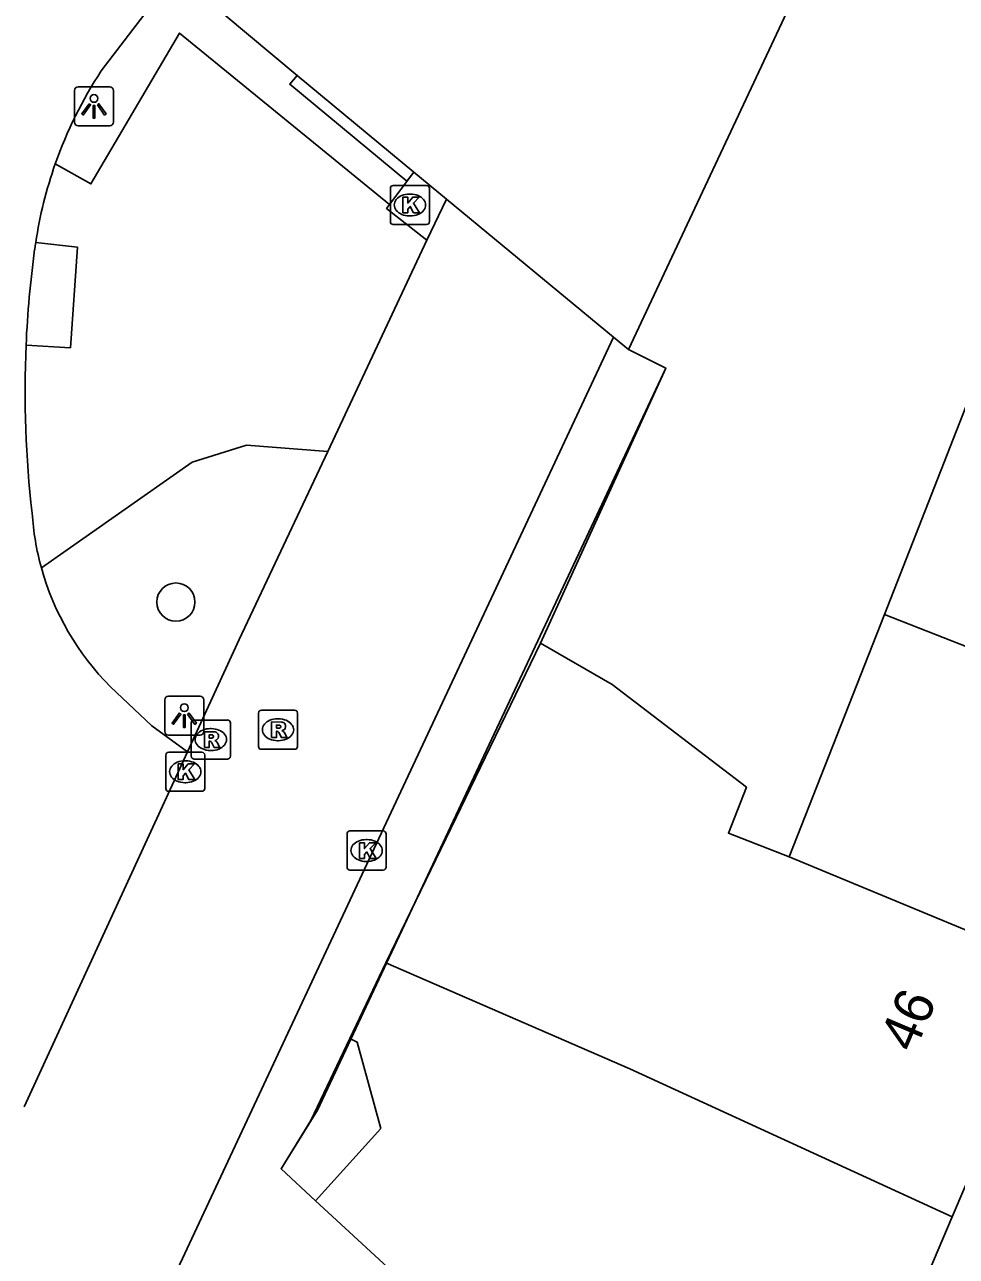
# Model space of a CAD drawing. Extents: x 160107 to 160928, y 382056 to 382918.
# Drawn here: x 160855.17 to 160879.01, y 382763.43 to 382794.93 of the extents above; entities that cross this region are included whole.
import ezdxf

# ---------------------------------------------------------------- set-up
doc = ezdxf.new("R2010")
doc.units = 0
for name, color, linetype in [('IMGEO_Boom', 7, 'Continuous'), ('IMGEO_Groenvoorziening', 7, 'Continuous'), ('IMGEO_Haag', 7, 'Continuous'), ('IMGEO_Kolk', 7, 'Continuous'), ('IMGEO_Lichtpunt', 7, 'Continuous'), ('IMGEO_Muur', 7, 'Continuous'), ('IMGEO_Pand', 7, 'Continuous'), ('IMGEO_Pand_nummerreeks', 7, 'Continuous'), ('IMGEO_Rijbaan_lokaal_open', 7, 'Continuous'), ('IMGEO_Rioolput', 7, 'Continuous'), ('IMGEO_Voetpad_open', 7, 'Continuous')]:
    doc.layers.add(name, color=color, linetype=linetype)

msp = doc.modelspace()

# ---------------------------------------------------------------- linework, layer by layer
at = {"layer": 'IMGEO_Boom'}
msp.add_circle((160859.037, 382780.163), 0.489, dxfattribs=at)
at = {"layer": 'IMGEO_Groenvoorziening'}
for points in [[(160865.463, 382789.419), (160864.429, 382790.234), (160864.504, 382790.333)], [(160855.596, 382781.037), (160859.451, 382783.744), (160860.847, 382784.179), (160862.922, 382784.019)]]:
    msp.add_lwpolyline(points, dxfattribs=at)
at = {"layer": 'IMGEO_Haag'}
for points in [[(160864.504, 382790.333), (160859.133, 382794.716), (160856.862, 382790.857), (160855.952, 382791.372)], [(160865.13, 382791.163), (160864.948, 382790.93), (160861.953, 382793.407), (160862.138, 382793.636)], [(160864.504, 382790.333), (160865.13, 382791.163)], [(160855.204, 382786.738), (160856.339, 382786.668), (160856.518, 382789.241), (160855.451, 382789.363)]]:
    msp.add_lwpolyline(points, dxfattribs=at)
at = {"layer": 'IMGEO_Kolk'}
for p, q in [((160864.526, 382789.894), (160864.526, 382790.746)), ((160864.601, 382790.82), (160865.453, 382790.82)), ((160865.527, 382790.746), (160865.527, 382789.894)), ((160865.014, 382790.6), (160865.039, 382790.6)), ((160865.453, 382789.82), (160864.601, 382789.82)), ((160865.037, 382790.04), (160865.012, 382790.04)), ((160858.778, 382775.398), (160858.778, 382776.25)), ((160858.853, 382776.324), (160859.705, 382776.324)), ((160859.779, 382776.25), (160859.779, 382775.398)), ((160859.266, 382776.104), (160859.291, 382776.104)), ((160859.705, 382775.324), (160858.853, 382775.324)), ((160859.289, 382775.544), (160859.264, 382775.544)), ((160863.417, 382773.383), (160863.417, 382774.235)), ((160863.492, 382774.309), (160864.344, 382774.309)), ((160863.905, 382774.089), (160863.93, 382774.089)), ((160864.418, 382774.235), (160864.418, 382773.383)), ((160863.928, 382773.529), (160863.903, 382773.529)), ((160864.344, 382773.309), (160863.492, 382773.309))]:
    msp.add_line(p, q, dxfattribs=at)
for points in [[(160864.526, 382789.894), (160864.526, 382790.746)], [(160864.601, 382790.82), (160865.453, 382790.82)], [(160865.527, 382790.746), (160865.527, 382789.894)], [(160864.847, 382790.52), (160864.97, 382790.52), (160864.97, 382790.369), (160865.1, 382790.52), (160865.264, 382790.52), (160865.118, 382790.369), (160865.271, 382790.12), (160865.119, 382790.12), (160865.034, 382790.284), (160864.97, 382790.217), (160864.97, 382790.12), (160864.847, 382790.12), (160864.847, 382790.52)], [(160865.453, 382789.82), (160864.601, 382789.82)], [(160858.778, 382775.398), (160858.778, 382776.25)], [(160858.853, 382776.324), (160859.705, 382776.324)], [(160859.779, 382776.25), (160859.779, 382775.398)], [(160859.099, 382776.024), (160859.222, 382776.024), (160859.222, 382775.873), (160859.352, 382776.024), (160859.516, 382776.024), (160859.37, 382775.873), (160859.523, 382775.624), (160859.371, 382775.624), (160859.286, 382775.788), (160859.222, 382775.721), (160859.222, 382775.624), (160859.099, 382775.624), (160859.099, 382776.024)], [(160859.705, 382775.324), (160858.853, 382775.324)], [(160863.417, 382773.383), (160863.417, 382774.235)], [(160863.492, 382774.309), (160864.344, 382774.309)], [(160863.738, 382774.009), (160863.861, 382774.009), (160863.861, 382773.858), (160863.991, 382774.009), (160864.155, 382774.009), (160864.009, 382773.858), (160864.162, 382773.609), (160864.01, 382773.609), (160863.925, 382773.773), (160863.861, 382773.706), (160863.861, 382773.609), (160863.738, 382773.609), (160863.738, 382774.009)], [(160864.418, 382774.235), (160864.418, 382773.383)], [(160864.344, 382773.309), (160863.492, 382773.309)]]:
    msp.add_lwpolyline(points, dxfattribs=at)
for centre, start, end in [((160864.603, 382790.744), 91.552, 178.448), ((160864.603, 382790.744), 91.552, 178.448), ((160865.451, 382790.744), 1.552, 88.448), ((160865.451, 382790.744), 1.552, 88.448), ((160864.603, 382789.896), 181.552, 268.448), ((160864.603, 382789.896), 181.552, 268.448), ((160865.451, 382789.896), 271.552, 358.448), ((160865.451, 382789.896), 271.552, 358.448), ((160858.855, 382776.248), 91.552, 178.448), ((160858.855, 382776.248), 91.552, 178.448), ((160859.703, 382776.248), 1.552, 88.448), ((160859.703, 382776.248), 1.552, 88.448), ((160858.855, 382775.4), 181.552, 268.448), ((160858.855, 382775.4), 181.552, 268.448), ((160859.703, 382775.4), 271.552, 358.448), ((160859.703, 382775.4), 271.552, 358.448), ((160863.494, 382774.233), 91.552, 178.448), ((160863.494, 382774.233), 91.552, 178.448), ((160864.342, 382774.233), 1.552, 88.448), ((160864.342, 382774.233), 1.552, 88.448), ((160863.494, 382773.385), 181.552, 268.448), ((160863.494, 382773.385), 181.552, 268.448), ((160864.342, 382773.385), 271.552, 358.448), ((160864.342, 382773.385), 271.552, 358.448)]:
    msp.add_arc(centre, 0.0765, start, end, dxfattribs=at)
for centre, major_axis, ratio, start_param, end_param in [((160865.013, 382790.32), (-0.387, 0.002), 0.722429, 4.712389, 7.853982), ((160865.038, 382790.32), (-0.39, 0.002), 0.717154, 1.570796, 4.712389), ((160859.265, 382775.824), (-0.387, 0.002), 0.722429, 4.712389, 7.853982), ((160859.29, 382775.824), (-0.39, 0.002), 0.717154, 1.570796, 4.712389), ((160863.904, 382773.809), (-0.387, 0.002), 0.722429, 4.712389, 7.853982), ((160863.929, 382773.809), (-0.39, 0.002), 0.717154, 1.570796, 4.712389)]:
    msp.add_ellipse(centre, major_axis=major_axis, ratio=ratio, start_param=start_param, end_param=end_param, dxfattribs=at)
at = {"layer": 'IMGEO_Lichtpunt'}
for p, q in [((160856.442, 382793.247), (160856.442, 382792.44)), ((160856.442, 382793.247), (160856.442, 382792.44)), ((160857.344, 382793.342), (160856.536, 382793.342)), ((160857.344, 382793.342), (160856.536, 382793.342)), ((160857.438, 382792.44), (160857.438, 382793.247)), ((160857.438, 382792.44), (160857.438, 382793.247)), ((160856.536, 382792.346), (160857.344, 382792.346)), ((160856.536, 382792.346), (160857.344, 382792.346)), ((160858.753, 382777.663), (160858.753, 382776.856)), ((160858.753, 382777.663), (160858.753, 382776.856)), ((160859.655, 382777.758), (160858.847, 382777.758)), ((160859.655, 382777.758), (160858.847, 382777.758)), ((160859.749, 382776.856), (160859.749, 382777.663)), ((160859.749, 382776.856), (160859.749, 382777.663)), ((160858.847, 382776.762), (160859.655, 382776.762)), ((160858.847, 382776.762), (160859.655, 382776.762))]:
    msp.add_line(p, q, dxfattribs=at)
for points in [[(160856.816, 382792.911), (160856.855, 382792.883), (160856.667, 382792.621), (160856.629, 382792.648), (160856.816, 382792.911)], [(160857.028, 382792.883), (160857.066, 382792.91), (160857.253, 382792.648), (160857.214, 382792.62), (160857.028, 382792.883)], [(160856.918, 382792.863), (160856.965, 382792.863), (160856.965, 382792.541), (160856.918, 382792.541), (160856.918, 382792.863)], [(160859.127, 382777.327), (160859.166, 382777.299), (160858.978, 382777.037), (160858.94, 382777.064), (160859.127, 382777.327)], [(160859.229, 382777.279), (160859.276, 382777.279), (160859.276, 382776.957), (160859.229, 382776.957), (160859.229, 382777.279)], [(160859.339, 382777.299), (160859.377, 382777.326), (160859.564, 382777.064), (160859.525, 382777.036), (160859.339, 382777.299)]]:
    msp.add_lwpolyline(points, dxfattribs=at)
for centre in [(160856.941, 382793.045), (160859.252, 382777.461)]:
    msp.add_circle(centre, 0.0994, dxfattribs=at)
for centre, start, end in [((160856.536, 382793.247), 90, 180), ((160856.536, 382793.247), 90, 180), ((160857.344, 382793.247), 0, 90), ((160857.344, 382793.247), 0, 90), ((160856.536, 382792.44), 180, 270), ((160856.536, 382792.44), 180, 270), ((160857.344, 382792.44), 270, 0), ((160857.344, 382792.44), 270, 360), ((160858.847, 382777.663), 90, 180), ((160858.847, 382777.663), 90, 180), ((160859.655, 382777.663), 0, 90), ((160859.655, 382777.663), 0, 90), ((160858.847, 382776.856), 180, 270), ((160858.847, 382776.856), 180, 270), ((160859.655, 382776.856), 270, 0), ((160859.655, 382776.856), 270, 360)]:
    msp.add_arc(centre, 0.0946, start, end, dxfattribs=at)
at = {"layer": 'IMGEO_Muur'}
for points in [[(160865.463, 382789.419), (160865.965, 382790.473)], [(160862.922, 382784.019), (160865.463, 382789.419)], [(160870.234, 382786.936), (160864.175, 382773.992)], [(160870.621, 382786.622), (160871.573, 382786.148), (160862.66, 382767.165), (160861.728, 382765.67), (160862.611, 382764.85)], [(160860.656, 382779.204), (160862.922, 382784.019)]]:
    msp.add_lwpolyline(points, dxfattribs=at)
at = {"layer": 'IMGEO_Pand'}
for points in [[(160878.006, 382802.366), (160870.621, 382786.622)], [(160859.026, 382796.237), (160862.138, 382793.636)], [(160862.138, 382793.636), (160865.13, 382791.163)], [(160865.13, 382791.163), (160865.965, 382790.473)], [(160870.234, 382786.936), (160865.965, 382790.473)], [(160870.621, 382786.622), (160870.234, 382786.936)], [(160877.168, 382779.848), (160879.654, 382786.178)], [(160874.732, 382773.645), (160877.168, 382779.848)], [(160877.168, 382779.848), (160886.026, 382776.373)], [(160864.409, 382770.935), (160868.368, 382779.113)], [(160868.368, 382779.113), (160870.2, 382778.054), (160873.638, 382775.428), (160873.177, 382774.255), (160874.732, 382773.645)], [(160874.732, 382773.645), (160881.607, 382770.804)], [(160863.489, 382768.997), (160864.409, 382770.935)], [(160878.904, 382764.441), (160870.655, 382768.224), (160864.409, 382770.935)], [(160881.607, 382770.804), (160879.55, 382765.961), (160878.904, 382764.441)], [(160862.611, 382764.85), (160864.28, 382766.698), (160863.68, 382768.906), (160863.489, 382768.997)], [(160875.47, 382756.281), (160868.142, 382759.756), (160862.611, 382764.85)], [(160878.904, 382764.441), (160877.92, 382762.125), (160875.47, 382756.281)]]:
    msp.add_lwpolyline(points, dxfattribs=at)
at = {"layer": 'IMGEO_Rijbaan_lokaal_open'}
for points in [[(160865.965, 382790.473), (160865.463, 382789.419)], [(160865.463, 382789.419), (160862.922, 382784.019)], [(160858.349, 382761.529), (160864.175, 382773.992), (160870.234, 382786.936)], [(160862.922, 382784.019), (160860.656, 382779.204), (160859.334, 382776.335)], [(160859.334, 382776.335), (160855.156, 382767.252)]]:
    msp.add_lwpolyline(points, dxfattribs=at)
at = {"layer": 'IMGEO_Rioolput'}
for p, q in [((160861.15, 382776.472), (160861.15, 382777.324)), ((160861.225, 382777.398), (160862.077, 382777.398)), ((160861.638, 382777.178), (160861.663, 382777.178)), ((160862.151, 382777.324), (160862.151, 382776.472)), ((160859.431, 382776.221), (160859.431, 382777.073)), ((160859.506, 382777.147), (160860.358, 382777.147)), ((160859.919, 382776.927), (160859.944, 382776.927)), ((160860.432, 382777.073), (160860.432, 382776.221)), ((160861.661, 382776.618), (160861.636, 382776.618)), ((160859.942, 382776.367), (160859.917, 382776.367)), ((160862.077, 382776.398), (160861.225, 382776.398)), ((160860.358, 382776.147), (160859.506, 382776.147))]:
    msp.add_line(p, q, dxfattribs=at)
for points in [[(160861.15, 382776.472), (160861.15, 382777.324)], [(160861.225, 382777.398), (160862.077, 382777.398)], [(160862.151, 382777.324), (160862.151, 382776.472)], [(160859.431, 382776.221), (160859.431, 382777.073)], [(160859.506, 382777.147), (160860.358, 382777.147)], [(160860.02, 382776.845), (160859.768, 382776.847), (160859.768, 382776.447)], [(160860.432, 382777.073), (160860.432, 382776.221)], [(160861.739, 382777.096), (160861.487, 382777.098), (160861.487, 382776.698)], [(160861.487, 382776.698), (160861.611, 382776.698), (160861.611, 382776.86), (160861.622, 382776.86)], [(160861.665, 382777.017), (160861.611, 382777.017), (160861.611, 382776.936)], [(160861.611, 382776.936), (160861.663, 382776.936)], [(160859.768, 382776.447), (160859.892, 382776.447), (160859.892, 382776.609), (160859.903, 382776.609)], [(160859.946, 382776.766), (160859.892, 382776.766), (160859.892, 382776.685)], [(160859.892, 382776.685), (160859.944, 382776.685)], [(160859.95, 382776.58), (160860.021, 382776.447), (160860.161, 382776.447), (160860.096, 382776.573)], [(160861.669, 382776.831), (160861.74, 382776.698), (160861.88, 382776.698), (160861.815, 382776.824)], [(160862.077, 382776.398), (160861.225, 382776.398)], [(160860.358, 382776.147), (160859.506, 382776.147)]]:
    msp.add_lwpolyline(points, dxfattribs=at)
for centre, radius, start, end in [((160861.227, 382777.322), 0.0765, 91.552, 178.448), ((160861.227, 382777.322), 0.0765, 91.552, 178.448), ((160862.075, 382777.322), 0.0765, 1.552, 88.448), ((160862.075, 382777.322), 0.0765, 1.552, 88.448), ((160859.508, 382777.071), 0.0765, 91.552, 178.448), ((160859.508, 382777.071), 0.0765, 91.552, 178.448), ((160860.019, 382776.735), 0.109, 350.3612, 89.416), ((160860.356, 382777.071), 0.0765, 1.552, 88.448), ((160860.356, 382777.071), 0.0765, 1.552, 88.448), ((160861.621, 382776.807), 0.0533, 26.0293, 88.6989), ((160861.647, 382777.125), 0.19, 274.7715, 282.9687), ((160861.671, 382776.921), 0.0964, 77.0061, 93.1865), ((160861.685, 382776.978), 0.0378, 276.6634, 79.6772), ((160861.738, 382776.986), 0.109, 350.3612, 89.416), ((160861.736, 382776.986), 0.112, 277.5842, 350.9817), ((160861.72, 382776.771), 0.108, 29.5134, 73.7905), ((160859.902, 382776.556), 0.0533, 26.0293, 88.6989), ((160859.928, 382776.874), 0.19, 274.7715, 282.9687), ((160859.952, 382776.67), 0.0964, 77.0061, 93.1865), ((160859.966, 382776.727), 0.0378, 276.6634, 79.6772), ((160860.017, 382776.735), 0.112, 277.5842, 350.9817), ((160860.001, 382776.52), 0.108, 29.5134, 73.7905), ((160859.508, 382776.223), 0.0765, 181.552, 268.448), ((160859.508, 382776.223), 0.0765, 181.552, 268.448), ((160860.356, 382776.223), 0.0765, 271.552, 358.448), ((160860.356, 382776.223), 0.0765, 271.552, 358.448), ((160861.227, 382776.474), 0.0765, 181.552, 268.448), ((160861.227, 382776.474), 0.0765, 181.552, 268.448), ((160862.075, 382776.474), 0.0765, 271.552, 358.448), ((160862.075, 382776.474), 0.0765, 271.552, 358.448)]:
    msp.add_arc(centre, radius, start, end, dxfattribs=at)
for centre, major_axis, ratio, start_param, end_param in [((160861.637, 382776.898), (-0.387, 0.002), 0.722429, 4.712389, 7.853982), ((160861.662, 382776.898), (-0.39, 0.002), 0.717154, 1.570796, 4.712389), ((160859.918, 382776.647), (-0.387, 0.002), 0.722429, 4.712389, 7.853982), ((160859.943, 382776.647), (-0.39, 0.002), 0.717154, 1.570796, 4.712389)]:
    msp.add_ellipse(centre, major_axis=major_axis, ratio=ratio, start_param=start_param, end_param=end_param, dxfattribs=at)
at = {"layer": 'IMGEO_Voetpad_open'}
for points in [[(160859.026, 382796.237), (160857.127, 382793.749)], [(160855.451, 382789.363), (160855.437, 382789.271), (160855.424, 382789.179)], [(160870.621, 382786.622), (160871.573, 382786.148), (160868.368, 382779.113)], [(160857.366, 382777.995), (160858.418, 382776.997), (160859.334, 382776.335)], [(160862.611, 382764.85), (160861.728, 382765.67), (160862.495, 382766.9), (160863.489, 382768.997)]]:
    msp.add_lwpolyline(points, dxfattribs=at)
for centre, radius, start, end in [((160878.164, 382788.105), 25.296, 153.9548, 168.4544), ((160866.373, 382787.7), 11.049, 146.8044, 160.5873), ((160866.317, 382787.72), 10.99, 160.5919, 171.4028), ((160881.902, 382785.562), 26.724, 172.2218, 177.4783), ((160882.096, 382785.549), 26.918, 177.4685, 186.6347), ((160862.288, 382782.894), 6.944, 183.7578, 195.5113), ((160862.285, 382782.893), 6.942, 195.5089, 224.8774)]:
    msp.add_arc(centre, radius, start, end, dxfattribs=at)

# ---------------------------------------------------------------- texts
at = {"layer": 'IMGEO_Pand_nummerreeks'}
msp.add_text('46', height=1, rotation=66.9845, dxfattribs=at).set_placement((160877.936, 382768.607))

doc.saveas('drawing.dxf')
